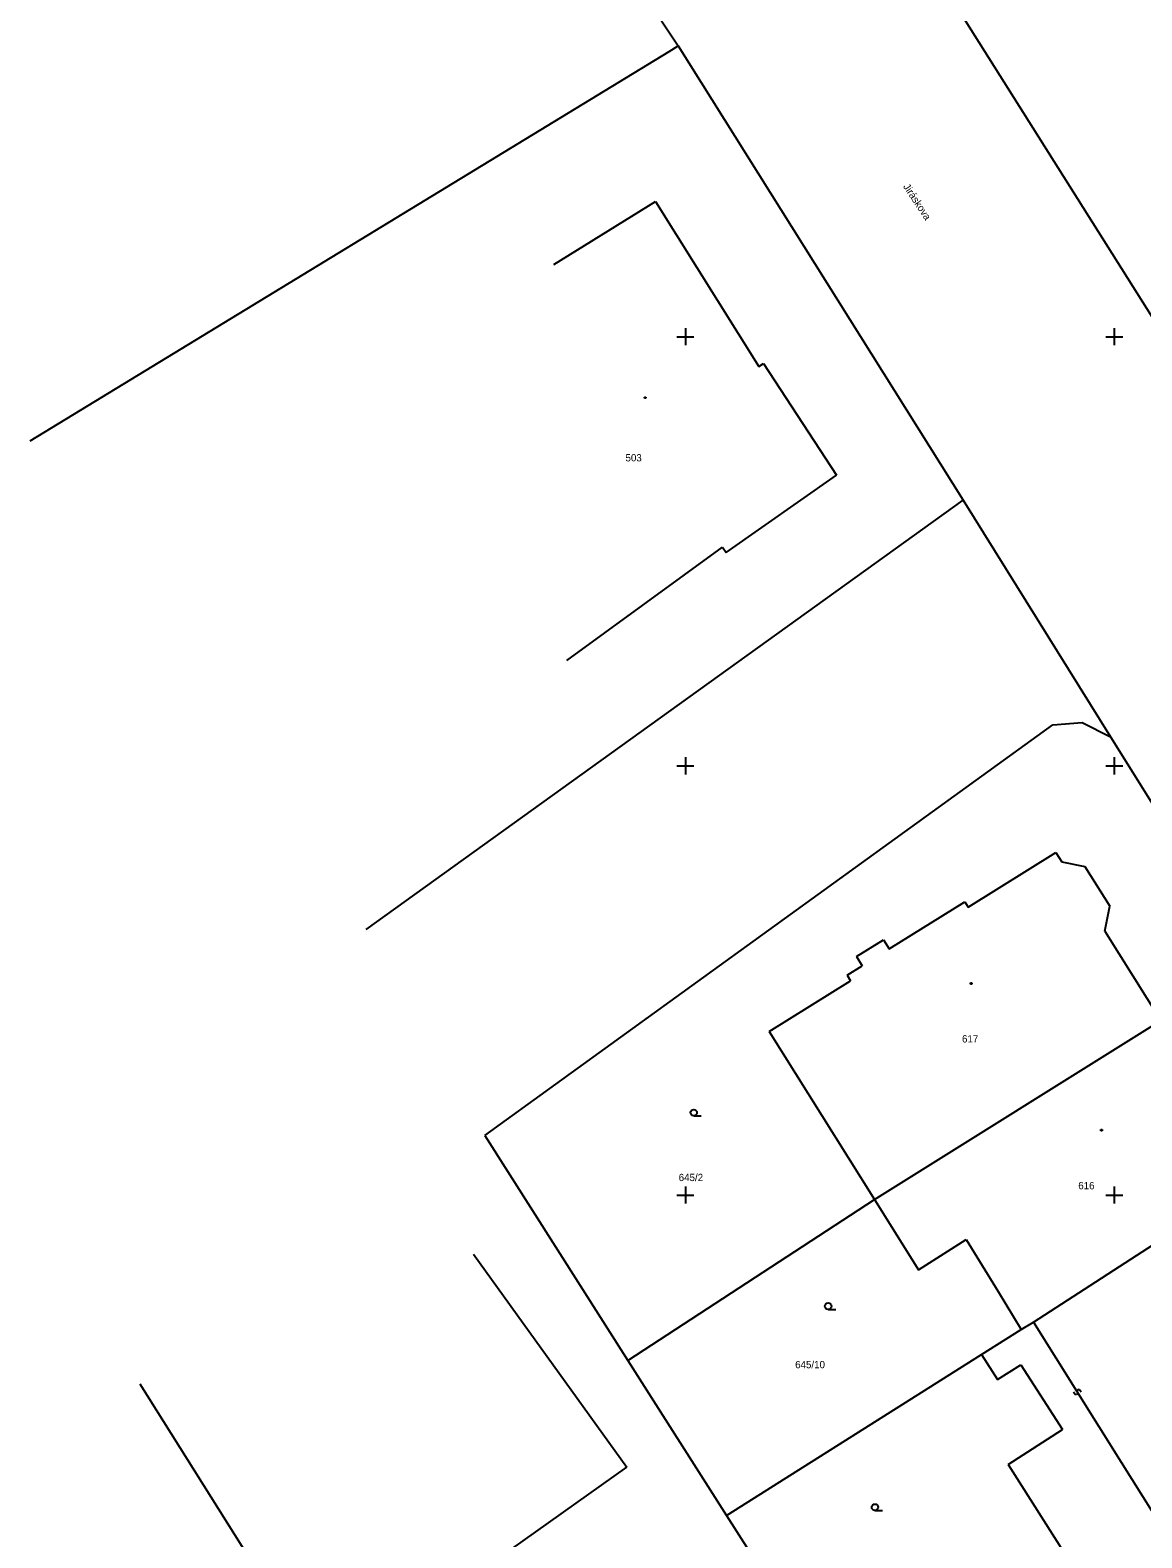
# Model space of a CAD drawing. Extents: x -492811 to -492366, y -1127107 to -1126748.
# Drawn here: x -492810.5 to -492758.7, y -1126976 to -1126905.7 of the extents above; entities that cross this region are included whole.
import ezdxf

# ---------------------------------------------------------------- set-up
doc = ezdxf.new("R2010")
doc.units = 0
doc.layers.add('katastrální mapa', color=7, linetype='Continuous')
doc.layers.add('síť', color=7, linetype='Continuous')

msp = doc.modelspace()

# ---------------------------------------------------------------- linework, layer by layer
at = {"layer": 'katastrální mapa'}
for p, q in [((-492776.99, -1126889.32), (-492757.33, -1126920.52)), ((-492782.48, -1126903.2), (-492780.34, -1126906.45)), ((-492780.76, -1126906.71), (-492780.34, -1126906.45)), ((-492780.34, -1126906.45), (-492767.04, -1126927.62)), ((-492810.55, -1126924.85), (-492780.76, -1126906.71)), ((-492786.13, -1126916.64), (-492781.39, -1126913.69)), ((-492781.39, -1126913.69), (-492776.57, -1126921.39)), ((-492776.57, -1126921.39), (-492776.35, -1126921.25)), ((-492776.35, -1126921.25), (-492772.95, -1126926.45)), ((-492781.9, -1126922.81), (-492781.84, -1126922.81)), ((-492781.9, -1126922.87), (-492781.9, -1126922.81)), ((-492781.84, -1126922.87), (-492781.9, -1126922.87)), ((-492781.84, -1126922.81), (-492781.84, -1126922.87)), ((-492778.09, -1126930.05), (-492772.95, -1126926.45)), ((-492794.89, -1126947.63), (-492767.04, -1126927.62)), ((-492767.04, -1126927.62), (-492760.18, -1126938.65)), ((-492785.53, -1126935.09), (-492778.27, -1126929.8)), ((-492778.27, -1126929.8), (-492778.09, -1126930.05)), ((-492789.35, -1126957.23), (-492762.86, -1126938.09)), ((-492762.86, -1126938.09), (-492761.5, -1126937.98)), ((-492761.5, -1126937.98), (-492760.18, -1126938.65)), ((-492760.18, -1126938.65), (-492753.58, -1126949.21)), ((-492766.81, -1126946.59), (-492762.72, -1126944.04)), ((-492762.72, -1126944.04), (-492762.45, -1126944.47)), ((-492762.45, -1126944.47), (-492761.37, -1126944.69)), ((-492761.37, -1126944.69), (-492760.21, -1126946.53)), ((-492770.5, -1126948.53), (-492766.97, -1126946.33)), ((-492766.97, -1126946.33), (-492766.81, -1126946.59)), ((-492760.44, -1126947.7), (-492760.21, -1126946.53)), ((-492760.44, -1126947.7), (-492757.83, -1126951.87)), ((-492772.02, -1126948.89), (-492770.76, -1126948.1)), ((-492770.76, -1126948.1), (-492770.5, -1126948.53)), ((-492772.46, -1126949.76), (-492771.76, -1126949.32)), ((-492772.02, -1126948.89), (-492771.76, -1126949.32)), ((-492776.09, -1126952.38), (-492772.3, -1126950.02)), ((-492772.46, -1126949.76), (-492772.3, -1126950.02)), ((-492766.71, -1126950.11), (-492766.65, -1126950.11)), ((-492766.71, -1126950.17), (-492766.71, -1126950.11)), ((-492766.65, -1126950.17), (-492766.71, -1126950.17)), ((-492766.65, -1126950.11), (-492766.65, -1126950.17)), ((-492771.18, -1126960.21), (-492757.83, -1126951.87)), ((-492776.09, -1126952.38), (-492771.18, -1126960.21)), ((-492779.61, -1126956.31), (-492779.26, -1126956.31)), ((-492760.63, -1126956.95), (-492760.57, -1126956.95)), ((-492760.63, -1126957.01), (-492760.63, -1126956.95)), ((-492760.57, -1126957.01), (-492760.63, -1126957.01)), ((-492760.57, -1126956.95), (-492760.57, -1126957.01)), ((-492789.35, -1126957.23), (-492782.68, -1126967.71)), ((-492763.77, -1126965.92), (-492753.28, -1126959.13)), ((-492782.68, -1126967.71), (-492771.18, -1126960.21)), ((-492771.18, -1126960.21), (-492769.13, -1126963.48)), ((-492769.13, -1126963.48), (-492766.91, -1126962.07)), ((-492766.91, -1126962.07), (-492765.42, -1126964.49)), ((-492789.88, -1126962.75), (-492782.73, -1126972.68)), ((-492765.42, -1126964.49), (-492764.34, -1126966.26)), ((-492773.34, -1126965.33), (-492772.99, -1126965.33)), ((-492764.34, -1126966.26), (-492763.77, -1126965.92)), ((-492763.77, -1126965.92), (-492759.68, -1126972.45)), ((-492766.19, -1126967.43), (-492764.34, -1126966.26)), ((-492778.08, -1126974.94), (-492766.19, -1126967.43)), ((-492766.19, -1126967.43), (-492765.44, -1126968.6)), ((-492782.68, -1126967.71), (-492778.08, -1126974.94)), ((-492765.44, -1126968.6), (-492764.36, -1126967.91)), ((-492764.36, -1126967.91), (-492762.42, -1126970.93)), ((-492805.44, -1126968.8), (-492778.81, -1127011.02)), ((-492761.82, -1126969.29), (-492761.91, -1126969.19)), ((-492761.77, -1126969.31), (-492761.82, -1126969.29)), ((-492761.73, -1126969.28), (-492761.77, -1126969.31)), ((-492761.72, -1126969.09), (-492761.73, -1126969.14)), ((-492761.73, -1126969.14), (-492761.72, -1126969.23)), ((-492761.72, -1126969.23), (-492761.73, -1126969.28)), ((-492761.68, -1126969.06), (-492761.72, -1126969.09)), ((-492761.63, -1126969.08), (-492761.68, -1126969.06)), ((-492761.54, -1126969.18), (-492761.63, -1126969.08)), ((-492764.95, -1126972.56), (-492762.42, -1126970.93)), ((-492759.68, -1126972.45), (-492756.93, -1126976.84)), ((-492788.75, -1126976.96), (-492782.73, -1126972.68)), ((-492764.95, -1126972.56), (-492760.7, -1126979.24)), ((-492778.08, -1126974.94), (-492776.46, -1126977.47)), ((-492771.16, -1126974.7), (-492770.81, -1126974.7))]:
    msp.add_line(p, q, dxfattribs=at)
for centre in [(-492779.61, -1126956.16), (-492773.34, -1126965.18), (-492771.16, -1126974.55)]:
    msp.add_circle(centre, 0.15, dxfattribs=at)
at = {"layer": 'síť'}
for p, q in [((-492780, -1126919.6), (-492780, -1126920.4)), ((-492760, -1126919.6), (-492760, -1126920.4)), ((-492780.4, -1126920), (-492779.6, -1126920)), ((-492760.4, -1126920), (-492759.6, -1126920)), ((-492780.4, -1126940), (-492779.6, -1126940)), ((-492780, -1126939.6), (-492780, -1126940.4)), ((-492760.4, -1126940), (-492759.6, -1126940)), ((-492760, -1126939.6), (-492760, -1126940.4)), ((-492780, -1126959.6), (-492780, -1126960.4)), ((-492760, -1126959.6), (-492760, -1126960.4)), ((-492780.4, -1126960), (-492779.6, -1126960)), ((-492760.4, -1126960), (-492759.6, -1126960))]:
    msp.add_line(p, q, dxfattribs=at)

# ---------------------------------------------------------------- texts
at = {"layer": 'katastrální mapa'}
msp.add_text('Jiráskova', height=0.34, rotation=303.327, dxfattribs=at).set_placement((-492769.86, -1126913))
for s, p in [('503', (-492782.79, -1126925.81)), ('617', (-492767.1, -1126952.89)), ('645/2', (-492780.31, -1126959.35)), ('616', (-492761.68, -1126959.73)), ('645/10', (-492774.88, -1126968.07))]:
    msp.add_text(s, height=0.34, dxfattribs=at).set_placement(p)

doc.saveas('drawing.dxf')
